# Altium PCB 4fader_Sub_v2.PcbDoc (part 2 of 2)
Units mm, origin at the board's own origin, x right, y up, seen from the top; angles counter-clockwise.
Board outline 100 x 45 mm, 2 copper layers (Top Layer, Bottom Layer); 98 components, 50 nets, 488 pads, 159 vias.
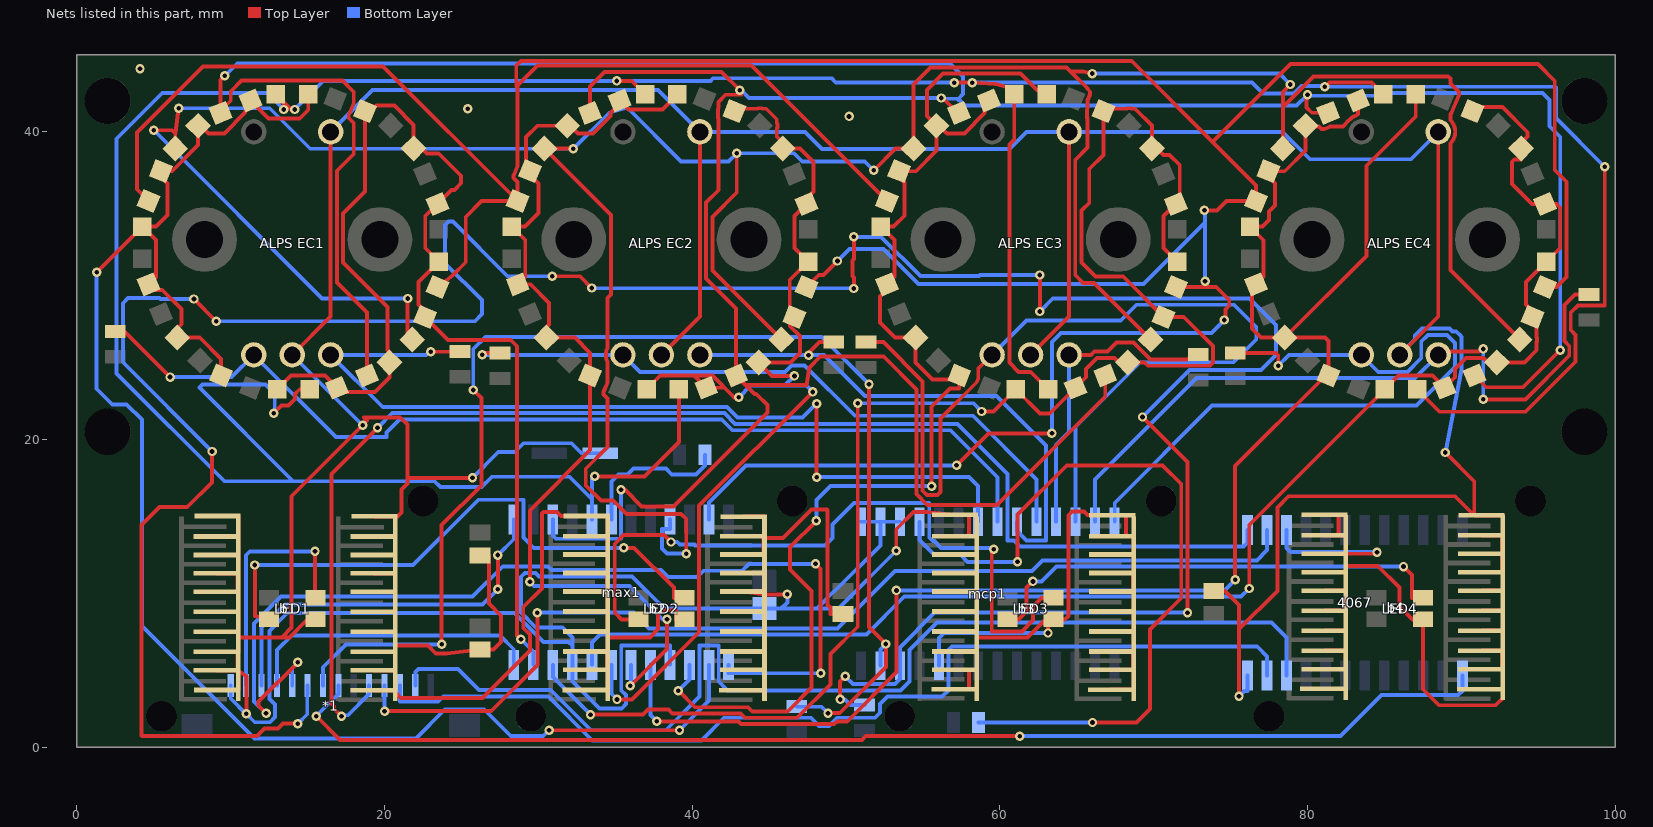
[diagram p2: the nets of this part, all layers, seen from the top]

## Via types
v1: diameter 0.61, hole 0.305, Top Layer to Bottom Layer, 159 vias

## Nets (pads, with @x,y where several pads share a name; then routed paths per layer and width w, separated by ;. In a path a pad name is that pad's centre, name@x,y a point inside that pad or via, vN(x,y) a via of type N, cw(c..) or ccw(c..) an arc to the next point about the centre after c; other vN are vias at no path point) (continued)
c1_5: *led5.2 *led13.2 *led21.2 *led29.2 *led37.2 *led45.2 *led53.2 *led61.2 max1.23 | length 259.9
  Top Layer w0.254: *led5.2@4.654,35.497 4.654,35.514 3.9,36.268 3.9,39.955 8.187,44.242 19.909,44.242 28.563,35.588 *led21.2@28.654,35.497 28.563,35.497 26.311,35.497 25.282,34.468 25.282,31.517 24.423,30.658 *led13.2@23.446,29.903 ; *led21.2@28.654,35.588 28.654,36.737 28.394,36.997 28.394,37.168 28.654,37.795 28.654,42.926 28.654,43.017 ; *led29.2@47.446,29.903 48.227,30.683 48.527,30.683 v1(49.442,31.598) ; *led37.2@52.654,35.497 43.853,44.298 29.934,44.298 28.654,43.017 ; v1(57.189,18.313) 59.271,20.396 v1(63.386,20.396) ; *led45.2@71.446,29.903 73.343,29.903 ; v1(73.3,34.9) 73.318,34.882 74.113,34.882 74.728,35.497 *led53.2@76.654,35.497 76.654,36.516 73.838,39.332 ; v1(73.343,30.284) 73.343,29.903 ; v1(74.6,27.768) 74.668,27.836 74.668,28.44 74.918,28.69 74.918,29.058 74.072,29.903 73.343,29.903 ; *led61.2@95.446,29.903 96.178,29.903 96.838,30.563 96.838,36.754 96.076,37.516 96.076,43.307 94.984,44.399 78.906,44.399 73.838,39.332 ; 28.654,43.017 28.563,42.926 28.563,43.017 28.563,44.298 28.859,44.594 68.577,44.594 73.838,39.332
  Bottom Layer w0.254: max1.23@41.1,14.8 41.1,15.905 43.508,18.313 v1(57.189,18.313) ; v1(49.442,31.598) 50.227,32.383 52.441,32.383 54.717,30.106 69.337,30.106 73.343,34.112 ; v1(63.386,20.396) 63.386,26.325 63.985,26.924 73.756,26.924 v1(74.6,27.768) ; v1(73.3,34.9) 73.343,34.857 73.343,34.112 ; v1(73.343,30.284) 73.343,34.112
c1_6: *led6.2 *led14.2 *led22.2 *led30.2 *led38.2 *led46.2 *led54.2 *led62.2 max1.21 | length 221.2
  Top Layer w0.254: v1(5,40.1) 6.174,40.1 6.396,39.878 ; *led6.2@6.396,38.906 6.396,39.878 ; v1(6.617,41.529) 6.404,39.934 6.396,39.878 ; v1(21.502,29.159) 21.502,26.796 *led14.2@21.804,26.494 ; v1@32.267,38.895 v1(32.278,38.906) *led22.2@30.396,38.906 34.71,34.593 34.71,29.413 34.5,29.204 34.5,25.969 ccw(c35.5,25.5) 34.5,25.03 34.5,23.713 34.24,23.085 34.24,22.913 34.5,22.653 34.5,19.513 33.084,18.098 33.084,17.018 34.078,16.024 34.869,16.024 35.729,15.164 39.282,15.164 39.612,14.834 v1(39.612,12.573) ; v1(42.9,38.6) 42.9,36.054 41.313,34.467 41.313,30.985 *led30.2@45.804,26.494 ; v1(51.804,37.49) 53.219,38.906 *led38.2@54.396,38.906 54.396,43.082 55.501,44.187 64.335,44.187 64.605,43.917 ; v1(66.002,43.784) 65.4,43.917 64.605,43.917 ; *led46.2@69.804,26.494 66.128,30.169 65.42,30.169 64.906,30.683 64.906,38.172 65.7,38.966 65.7,40.876 65.674,40.902 65.674,41.073 65.7,41.926 65.7,42.028 65.86,42.415 65.86,42.587 65.7,42.822 65.626,42.896 64.605,43.917 ; *led54.2@78.396,38.906 78.396,41.604 78.396,42.595 v1(78.88,43.078) ; 78.396,41.623 80.38,43.606 89.145,43.606 89.294,43.458 89.294,43.153 89.86,42.587 89.86,42.415 89.359,41.204 89.294,41.103 89.294,40.768 cw(c88.5,40) 89.294,39.233 89.294,31.003 *led62.2@93.804,26.494
  Bottom Layer w0.254: v1(5,40.1) 15.941,29.159 v1(21.502,29.159) ; v1(6.617,41.529) 12.535,41.529 15.169,38.895 32.267,38.895 v1(32.278,38.906) 34.608,41.236 35.776,41.58 39.282,38.075 42.375,38.075 42.908,38.608 46.622,38.608 47.156,38.075 51.22,38.075 v1(51.804,37.49) ; max1.21@38.56,14.8 38.56,14.173 38.037,14.173 38.037,12.903 38.367,12.573 v1(39.612,12.573) ; v1(66.002,43.784) 78.174,43.784 v1(78.88,43.078)
c1_7: *led7.2 *led15.2 *led23.2 *led31.2 *led39.2 *led47.2 *led55.2 *led63.2 max1.15 | length 258.3
  Top Layer w0.254: v1(9.614,43.637) 9.346,43.369 *led7.2@9.346,41.236 9.346,41.365 10,42.019 10,42.626 10.707,43.332 17.26,43.332 17.926,42.667 18,42.592 18,41.86 17.674,41.073 17.674,40.902 18,40.576 18,38.561 16.906,37.467 16.906,30.206 18.854,28.259 *led15.2@18.854,24.164 ; *led23.2@33.346,41.236 33.346,42.934 34.303,43.891 41.909,43.891 v1(43.1,42.7) ; v1(35.37,16.739) 35.624,16.739 36.716,15.646 38.773,15.646 44.884,21.758 44.884,22.242 44.166,22.96 44.058,22.96 43.472,23.546 ; 43.204,42.406 42.165,42.406 41.774,42.015 41.7,41.941 41.674,41.073 41.674,40.902 41.7,40.876 41.7,36.201 40.906,35.408 40.906,30.472 42.854,28.524 *led31.2@42.854,24.164 43.472,23.546 ; v1(56.2,42.2) 56.291,42.2 57.255,41.236 *led39.2@57.346,41.236 ; *led47.2@66.854,24.164 66.854,22.797 59.805,15.748 55.284,15.748 54.572,16.459 54.572,23.259 52.452,25.379 48.329,25.379 47.638,24.689 47.439,23.546 43.472,23.546 ; v1(80,42.4) 79.932,42.332 79.932,41.801 79.929,41.798 79.929,41.587 80.28,41.236 *led55.2@81.346,41.236 ; *led63.2@90.854,24.164 91.625,23.393 94.019,23.393 v1(96.432,25.806)
  Bottom Layer w0.254: v1(9.614,43.637) 10.427,44.45 56.773,44.45 57.616,43.607 57.616,42.464 57.302,42.15 56.25,42.15 v1(56.2,42.2) 43.696,42.2 43.196,42.7 v1(43.1,42.7) ; max1.15@30.94,14.8 30.94,13.759 31.154,13.546 35.379,13.546 35.379,16.729 v1(35.37,16.739) ; 57.302,42.064 57.39,42.064 ; 57.39,42.062 57.752,41.7 79.3,41.7 v1(80,42.4) 80.058,42.342 84.766,42.342 84.944,42.519 95.289,42.519 95.746,42.062 95.746,40.361 96.432,39.675 v1(96.432,25.806)
c1_8: *led8.2 *led16.2 *led24.2 *led32.2 *led40.2 *led48.2 *led56.2 *led64.2 max1.17 | length 242.9
  Top Layer w0.254: v1(12.8,21.7) 13.303,22.203 13.751,22.203 14.186,22.638 14.186,22.962 14.488,23.264 *led16.2@15.134,23.264 ; *led8.2@12.941,42.436 *led8.2@13.45,41.927 ; v1(13.45,41.453) *led8.2@13.45,41.927 ; v1(14.16,41.453) 13.924,41.453 13.687,41.69 *led8.2@13.45,41.927 ; v1(33.668,17.602) 36.894,17.602 39.134,19.842 *led32.2@39.134,23.264 ; v1(35.091,43.307) 36.07,43.307 *led24.2@36.941,42.436 ; v1(57.032,43.197) v1(58.2,43.197) ; v1@58.2,43.2 v1(58.2,43.197) ; *led48.2@63.134,23.264 62.013,24.384 61.227,24.384 60.618,24.994 60.618,39.167 60.941,39.49 *led40.2@60.941,42.436 60.468,42.909 59.727,43.103 v1(58.2,43.197) ; v1(81.115,42.926) 81.168,42.926 81.442,43.2 84.177,43.2 *led56.2@84.941,42.436 ; *led64.2@87.134,23.264 88.596,21.801 94.174,21.801 97.422,25.049 97.422,26.797 97.117,27.102 97.117,28.245 97.575,28.702 99.327,28.702 v1(99.327,37.719)
  Bottom Layer w0.254: v1(12.8,21.7) 12.866,21.766 12.866,22.962 12.256,23.571 8.167,23.571 7.963,23.368 14.052,17.279 ; v1(13.45,41.453) 12.383,42.52 5.55,42.52 2.579,39.548 2.579,24.293 9.592,17.279 14.052,17.279 ; v1(14.16,41.453) 16.014,43.307 v1(35.091,43.307) 41.195,43.307 41.372,43.484 49.044,43.484 49.332,43.197 v1(57.032,43.197) ; max1.17@33.48,14.8 33.48,16.114 ; v1(33.668,17.602) 33.48,17.414 33.48,16.114 ; v1(58.2,43.197) 76.402,43.197 77.104,42.494 79.122,42.494 79.612,42.984 81.057,42.984 v1(81.115,42.926) 96.102,42.926 96.152,42.876 96.152,40.894 v1(99.327,37.719) ; 14.052,17.279 23.254,17.279 23.626,16.908 26.308,16.908 26.978,17.577 32.017,17.577 33.48,16.114
clk11: *1.3 max1.13 | length 25.1
  Top Layer w0.254: v1(27.369,10.262) v1(27.369,12.482)
  Bottom Layer w0.254: *1.3@12,4 12,7.772 13.499,9.271 26.378,9.271 v1(27.369,10.262) ; v1(27.369,12.482) 28.4,13.513 max1.13@28.4,14.8
cs12: *1.4 max1.12 | length 19.5
  Bottom Layer w0.254: *1.4@13,4 13,6.299 13.966,7.265 27.495,7.265 28.4,6.361 max1.12@28.4,5.35
DATA: *1.2 LED1.2 | length 16.1
  Top Layer w0.254: v1(15.482,12.725) 15.482,9.7 LED1.2@15.5,9.7
  Bottom Layer w0.254: *1.2@11,4 11,4.547 10.986,4.547 10.986,12.471 11.24,12.725 v1(15.482,12.725)
din13: *1.5 max1.1 | length 64.8
  Top Layer w0.254: v1(12.3,2.2) 12.3,2.206 11.818,2.688 11.818,2.966 v1(14.364,5.512) ; v1(48.019,11.913) 48.349,11.582 v1(48.349,4.801)
  Bottom Layer w0.254: v1(12.3,2.2) 12.291,2.2 11.519,2.972 11.519,8.026 13.272,9.779 25.732,9.779 27.687,11.735 30.614,11.735 30.842,11.506 37.971,11.506 38.428,11.049 40.315,11.049 40.729,11.463 43.241,11.463 43.691,11.913 v1(48.019,11.913) ; *1.5@14,4 14,5.148 v1(14.364,5.512) ; max1.1@42.37,5.35 42.37,4.801 v1(48.349,4.801)
e0: "ALPS EC1.B1" mcp1.21 r1.1 | length 60
  Top Layer w0.254: v1(23,25.7) 24.875,25.7 r1.1@24.9,25.725 ; v1(48.095,17.551) v1(48.095,22.327)
  Bottom Layer w0.254: v1(23,25.7) 22.904,25.7 22.703,25.5 16.5,25.5 19.886,22.113 42.26,22.113 42.958,21.416 47.185,21.416 v1(48.095,22.327) ; v1(48.095,17.551) 57.996,17.551 58.58,16.967 mcp1.21@58.58,14.65
e1: "ALPS EC1.A1" mcp1.22 r2.1 | length 66.5
  Top Layer w0.254: r2.1@2.5,27.025 3.087,27.025 v1(6.058,24.054)
  Bottom Layer w0.254: v1(6.058,24.054) 10.054,24.054 11.5,25.5 16.832,20.168 20.13,20.168 20.13,20.448 20.983,21.301 41.923,21.301 42.627,20.597 56.795,20.597 59.85,17.542 mcp1.22@59.85,14.65
e2: "ALPS EC2.B1" mcp1.23 r3.1 | length 36
  Top Layer w0.254: v1(47.567,25.475) 47.635,25.543 47.635,25.676 48.284,26.325 r3.1@49.2,26.325
  Bottom Layer w0.254: 40.5,25.5 47.543,25.5 v1(47.567,25.475) ; v1@47.458,25.5 48.58,25.5 51.245,22.835 59.779,22.835 63.005,19.609 63.005,13.437 61.735,13.437 61.12,14.052 mcp1.23@61.12,14.65
e3: "ALPS EC2.A1" mcp1.24 r4.1 | length 43.7
  Top Layer w0.254: v1(26.355,25.5) 26.48,25.625 r4.1@27.5,25.625
  Bottom Layer w0.254: v1(26.355,25.5) 35.5,25.5 36.615,24.384 46.038,24.384 46.47,24.816 47.308,24.816 50.585,21.539 58.255,21.539 62.39,17.405 mcp1.24@62.39,14.65
e4: "ALPS EC3.B1" mcp1.25 r5.1 | length 20.5
  Top Layer w0.254: 64.5,25.5 65.934,25.5 66.14,25.706 66.996,25.706 67.59,26.3 68.684,26.3 69.784,25.2 72.203,25.2 72.23,25.227 72.602,25.227 r5.1@72.9,25.525
  Bottom Layer w0.254: mcp1.25@63.66,14.65 63.66,19.634 64.5,20.474 64.5,25.5
e5: "ALPS EC3.A1" mcp1.26 r6.1 | length 63.7
  Top Layer w0.254: r6.1@51.3,26.325 52.428,26.325 54.979,23.774 54.979,16.662 55.258,16.383 55.944,16.383 56.147,16.586 56.147,21.364 58.503,23.72 58.6,23.955 58.6,24.6 59.5,25.5
  Bottom Layer w0.254: 59.5,25.5 61.737,27.737 67.863,27.737 68.884,28.759 75.217,28.759 76.67,27.305 76.67,26.492 75.197,25.019 69.127,25.019 64.93,20.822 mcp1.26@64.93,14.65
e6: "ALPS EC4.B1" mcp1.27 r7.1 | length 47.1
  Top Layer w0.254: 88.5,25.5 88.5,25.806 88.6,25.706 91.154,25.706 91.332,25.884 v1(91.428,25.884) ; v1(91.428,22.606) 94.171,22.606 97.016,25.451 97.016,26.086 96.711,26.391 96.711,28.739 97.397,29.425 r7.1@98.3,29.425
  Bottom Layer w0.254: mcp1.27@66.2,14.65 66.2,17.393 72.796,23.989 86.989,23.989 88.5,25.5 ; v1(91.428,22.606) v1(91.428,25.884)
e7: "ALPS EC4.A1" mcp1.28 r8.1 | length 46.2
  Top Layer w0.254: r8.1@75.3,25.625 77.951,25.625 78.1,25.476 v1(78.1,24.8)
  Bottom Layer w0.254: mcp1.28@67.47,14.65 67.47,15.869 73.8,22.2 87.1,22.2 89.604,24.704 89.604,25.468 ccw(c88.5,25.5) 89.604,25.532 89.604,26.269 89.073,26.8 87.839,26.8 87.395,26.356 87.395,25.285 86.506,24.395 84.604,24.395 83.499,25.5 78.8,25.5 v1(78.1,24.8)
GND: 4067.12 4067.15 "ALPS EC1.C1" "ALPS EC1.W1" "ALPS EC2.C1" "ALPS EC2.W1" "ALPS EC3.C1" "ALPS EC3.W1" "ALPS EC4.C1" "ALPS EC4.W1" *1.1 b1.2 b2.2 b3.2 b4.2 C1.1 C2.2 C3.1 C4.2 C5.2 C6.1 LED1.1 LED2.1 LED3.1 LED4.1 max1.4 max1.9 mcp1.10 mcp1.15 mcp1.16 mcp1.17 pad.19 pad.20 pad.21 pad.22 pad.23 pad.24 pad.25 pad.26 pad.27 | length 675.8
  Top Layer w0.254: pad.27@9.091,4.991 b1.2@10.453,4.991 ; pad.26@9.091,6.191 b1.2@10.453,6.191 ; pad.25@9.091,7.491 b1.2@10.5,7.491 ; pad.24@9.091,8.791 b1.2@10.5,8.791 ; pad.23@9.091,10.091 b1.2@10.453,10.091 ; pad.22@9.091,11.291 10.453,11.291 b1.2@10.453,10.091 ; pad.21@9.091,12.491 10.478,12.491 b1.2@10.5,12.47 ; pad.20@9.091,13.691 b1.2@10.5,13.691 ; pad.27@9.113,3.708 10.5,3.708 b1.2@10.5,4.958 ; pad.19@9.142,15.024 10.5,15.024 b1.2@10.5,13.691 ; v1(11.016,2.164) 11.037,2.184 11.037,4.585 b1.2@10.5,4.958 ; 14,25.5 16.5,28 16.5,40 ; LED1.1@15.5,8.3 14.974,8.3 13.812,7.137 13.323,7.137 ; pad.27@19.273,3.683 b1.2@20.7,3.683 ; pad.27@19.291,4.991 b1.2@20.7,4.991 ; pad.26@19.291,6.191 b1.2@20.7,6.191 ; pad.25@19.291,7.491 b1.2@20.7,7.491 ; pad.24@19.291,8.791 b1.2@20.7,8.791 ; pad.23@19.291,10.091 b1.2@20.7,10.091 ; pad.22@19.291,11.291 b1.2@20.7,11.291 ; pad.21@19.291,12.491 b1.2@20.7,12.491 ; pad.20@19.291,13.691 20.663,13.691 b1.2@20.663,14.999 ; pad.19@19.353,14.999 b1.2@20.663,14.999 ; v1(25.718,17.501) 21.486,17.501 ; C1.1@26.2,12.45 26.785,12.45 26.785,9.322 27.567,8.54 27.567,6.827 27.09,6.35 C2.2@26.2,6.35 24.042,6.096 23.331,6.096 22.823,6.604 b1.2@20.7,6.604 ; pad.27@33.065,3.708 34.5,3.708 b2.2@34.5,6.217 ; pad.27@33.094,5.017 34.456,5.017 b2.2@34.456,6.217 ; pad.26@33.094,6.217 b2.2@34.456,6.217 ; pad.25@33.094,7.517 b2.2@34.5,7.517 ; pad.24@33.094,8.817 b2.2@34.5,8.817 ; pad.23@33.094,10.117 b2.2@34.456,10.117 ; pad.22@33.094,11.317 34.456,11.317 b2.2@34.456,10.117 ; pad.21@33.094,12.517 b2.2@34.5,12.517 ; pad.20@33.094,13.717 b2.2@34.5,13.717 ; 38,25.5 40.5,28 40.5,40 ; LED2.1@39.5,8.3 38.951,8.3 38.951,8.894 38.062,8.894 37.783,8.615 37.783,7.671 37.25,7.137 b2.2@34.5,7.137 ; pad.27@43.25,3.683 44.7,3.683 b2.2@44.7,5.017 ; pad.27@43.294,5.017 b2.2@44.7,5.017 ; pad.26@43.294,6.217 b2.2@44.7,6.217 ; pad.25@43.294,7.517 b2.2@44.7,7.517 ; pad.24@43.294,8.817 b2.2@44.7,8.817 ; pad.23@43.294,10.117 b2.2@44.7,9.931 ; pad.22@43.294,11.317 44.692,11.317 b2.2@44.692,13.717 ; pad.21@43.294,12.517 44.641,12.517 b2.2@44.641,13.717 ; pad.20@43.294,13.717 b2.2@44.641,13.717 ; pad.19@43.352,14.986 44.7,14.986 b2.2@44.7,13.589 ; v1(46.19,9.931) b2.2@44.7,9.931 ; C3.1@49.8,8.65 48.984,8.65 48.984,9.068 48.807,9.246 48.807,15.392 48.756,15.443 47.753,15.443 45.898,13.589 b2.2@44.7,13.589 ; v1(53.265,12.765) 53.265,14.161 54.395,15.291 55.233,15.291 pad.19@57.097,15.1 58.001,15.1 pad.20@58.001,13.717 ; pad.27@57.068,3.759 pad.27@58.001,3.759 ; pad.27@57.097,5.017 58.001,5.017 pad.27@58.001,3.759 ; pad.26@57.097,6.217 b3.2@58.5,6.217 ; pad.25@57.097,7.517 b3.2@58.5,7.517 ; pad.24@57.097,8.817 b3.2@58.5,8.817 ; pad.23@57.097,10.117 b3.2@58.5,10.117 ; pad.22@57.097,11.317 b3.2@58.5,11.317 ; pad.21@57.097,12.517 b3.2@58.5,12.517 ; pad.20@57.097,13.717 pad.20@58.001,13.717 ; 62,25.5 64.5,28 64.5,40 ; v1(63.132,7.417) LED3.1@63.132,8.3 ; pad.27@67.228,3.733 68.7,3.733 b3.2@68.7,6.217 ; pad.27@67.297,5.017 68.644,5.017 b3.2@68.644,6.217 ; pad.26@67.297,6.217 b3.2@68.644,6.217 ; pad.25@67.297,7.517 b3.2@68.7,7.517 ; pad.24@67.297,8.817 68.669,8.817 68.669,8.969 b3.2@68.7,9 ; pad.23@67.297,10.117 b3.2@68.644,10.117 ; pad.22@67.297,11.317 68.644,11.317 b3.2@68.644,10.117 ; pad.21@67.297,12.517 b3.2@68.7,12.517 ; pad.20@67.297,13.717 pad.20@68.212,13.717 ; C4.2@73.9,10.15 74.638,10.15 75.553,9.236 75.553,7.671 ; v1(75.553,3.302) 75.553,7.671 ; pad.27@81.02,3.784 82.5,3.784 b4.2@82.5,6.267 ; pad.27@81.1,5.067 82.462,5.067 b4.2@82.462,6.267 ; pad.26@81.1,6.267 b4.2@82.462,6.267 ; pad.25@81.1,7.567 b4.2@82.5,7.567 ; pad.24@81.1,8.867 b4.2@82.5,8.867 ; pad.23@81.1,10.167 b4.2@82.5,10.167 ; pad.22@81.1,11.367 b4.2@82.5,11.367 ; pad.21@81.1,12.567 b4.2@82.5,12.567 ; pad.20@81.1,13.767 pad.20@82.004,13.767 ; pad.19@81.1,15.1 82.004,15.1 pad.20@82.004,13.767 ; v1(84.519,12.675) 84.412,12.567 b4.2@82.5,12.567 ; 86,25.5 88.5,28 88.5,40 ; v1(88.964,19.152) 90.844,17.272 pad.19@90.844,15.062 ; pad.27@91.206,3.759 b4.2@92.7,3.759 ; pad.27@91.3,5.067 92.647,5.067 b4.2@92.647,6.267 ; pad.26@91.3,6.267 b4.2@92.647,6.267 ; pad.25@91.3,7.567 b4.2@92.7,7.567 ; pad.24@91.3,8.867 b4.2@92.7,8.867 ; pad.23@91.3,10.167 b4.2@92.7,10.167 ; pad.22@91.3,11.367 92.647,11.367 b4.2@92.647,12.567 ; pad.21@91.3,12.567 b4.2@92.647,12.567 ; pad.20@91.3,13.767 b4.2@92.647,13.767 ; b1.2@10.453,4.991 b1.2@10.5,4.958 ; b1.2@10.453,4.991 b1.2@10.453,6.191 ; b1.2@10.453,6.191 10.5,6.191 b1.2@10.5,7.137 ; b1.2@10.453,10.091 10.478,10.091 b1.2@10.5,10.07 ; b1.2@10.5,7.137 13.323,7.137 ; b1.2@10.5,7.137 b1.2@10.5,7.491 ; b1.2@10.5,7.491 b1.2@10.5,8.791 ; b1.2@10.5,8.791 b1.2@10.5,9 b1.2@10.5,10.07 ; b1.2@10.5,10.07 10.5,10.091 10.5,11.291 10.5,12.462 b1.2@10.5,12.47 ; b1.2@10.5,12.47 b1.2@10.5,13.691 ; 13.323,7.137 13.958,7.772 13.958,16.307 v1(18.575,20.924) 18.873,21.222 18.657,21.438 21.019,21.438 21.486,20.971 21.486,17.501 ; b1.2@20.663,14.999 b1.2@20.7,14.999 ; b1.2@20.7,3.683 20.7,3.556 21.055,3.2 26.378,3.2 29.452,6.274 29.452,7.315 29.02,7.747 29.02,9.099 30.239,10.318 30.239,15.189 30.341,15.291 31.217,15.291 31.484,15.024 pad.19@33.145,15.024 34.5,15.024 b2.2@34.5,13.717 ; b1.2@20.7,3.683 b1.2@20.7,4.991 ; b1.2@20.7,4.991 b1.2@20.7,6.191 ; b1.2@20.7,6.191 b1.2@20.7,6.604 ; b1.2@20.7,6.604 b1.2@20.7,7.491 ; b1.2@20.7,7.491 b1.2@20.7,8.791 ; b1.2@20.7,8.791 b1.2@20.7,9 b1.2@20.7,10.091 ; b1.2@20.7,10.091 b1.2@20.7,11.291 ; b1.2@20.7,11.291 b1.2@20.7,12.491 ; b1.2@20.7,12.491 b1.2@20.7,14.999 ; b1.2@20.7,14.999 20.854,14.999 21.095,15.24 21.095,16.741 21.486,17.132 21.486,17.501 ; b2.2@34.456,6.217 b2.2@34.5,6.217 ; b2.2@34.456,10.117 b2.2@34.5,10.117 ; b2.2@34.5,6.217 b2.2@34.5,7.137 ; b2.2@34.5,7.137 b2.2@34.5,7.517 ; b2.2@34.5,7.517 b2.2@34.5,8.817 ; b2.2@34.5,8.817 b2.2@34.5,9 b2.2@34.5,10.117 ; b2.2@34.5,10.117 34.5,11.317 b2.2@34.5,12.517 ; b2.2@34.5,12.517 b2.2@34.5,13.717 ; b2.2@44.641,13.717 b2.2@44.692,13.717 ; b2.2@44.692,13.717 44.696,12.521 44.7,11.321 b2.2@44.7,11.27 ; b2.2@44.7,5.017 b2.2@44.7,6.217 ; b2.2@44.7,6.217 b2.2@44.7,7.517 ; b2.2@44.7,7.517 b2.2@44.7,8.817 ; b2.2@44.7,8.817 b2.2@44.7,9 b2.2@44.7,9.931 ; b2.2@44.7,9.931 44.7,10.117 b2.2@44.7,11.27 ; b2.2@44.7,11.27 44.7,11.317 44.7,12.517 b2.2@44.7,13.589 ; pad.27@58.001,3.759 58.5,3.759 b3.2@58.5,6.217 ; pad.20@58.001,13.717 b3.2@58.5,13.717 ; b3.2@58.5,6.217 b3.2@58.5,7.114 ; b3.2@58.5,7.114 b3.2@58.5,7.517 ; b3.2@58.5,7.114 61.794,7.114 62.98,8.3 LED3.1@63.132,8.3 ; b3.2@58.5,7.517 b3.2@58.5,8.817 ; b3.2@58.5,8.817 b3.2@58.5,9 b3.2@58.5,10.117 ; b3.2@58.5,10.117 b3.2@58.5,11.317 ; b3.2@58.5,11.317 b3.2@58.5,12.517 ; b3.2@58.5,12.517 58.509,12.517 58.509,13.717 b3.2@58.5,13.717 ; b3.2@58.5,12.517 b3.2@58.5,13.717 ; LED3.1@63.132,8.3 LED3.1@63.5,8.3 64.218,8.3 64.453,8.534 64.453,15.074 64.682,15.303 65.47,15.303 65.698,15.075 pad.19@67.308,15.075 68.212,15.075 pad.20@68.212,13.717 ; pad.20@68.212,13.717 68.7,13.717 b3.2@68.7,12.517 ; b3.2@68.644,6.217 b3.2@68.7,6.217 ; b3.2@68.644,10.117 68.667,10.117 b3.2@68.7,10.084 ; b3.2@68.7,6.217 b3.2@68.7,7.517 ; b3.2@68.7,7.517 68.7,8.817 b3.2@68.7,9 ; b3.2@68.7,9 b3.2@68.7,10.084 ; b3.2@68.7,10.084 68.7,10.117 68.7,11.317 b3.2@68.7,12.517 ; 75.553,7.671 78.042,10.16 78.042,15.57 78.779,16.307 89.599,16.307 pad.19@90.844,15.062 ; pad.20@82.004,13.767 82.5,13.767 b4.2@82.5,12.567 ; b4.2@82.462,6.267 b4.2@82.5,6.267 ; b4.2@82.5,6.267 b4.2@82.5,7.567 ; b4.2@82.5,7.567 b4.2@82.5,8.867 ; b4.2@82.5,8.867 b4.2@82.5,9.075 b4.2@82.5,10.167 ; b4.2@82.5,10.167 b4.2@82.5,11.367 ; b4.2@82.5,11.367 b4.2@82.5,11.786 ; b4.2@82.5,11.786 84.57,11.786 85.992,10.363 85.992,9.138 86.83,8.3 LED4.1@87.5,8.3 87.516,8.3 87.516,3.761 88.558,2.72 92.219,2.72 92.7,3.2 b4.2@92.7,3.759 ; b4.2@82.5,11.786 b4.2@82.5,12.567 ; pad.19@90.844,15.062 pad.19@91.307,15.062 92.7,15.062 b4.2@92.7,11.072 ; b4.2@92.647,6.267 b4.2@92.7,6.267 ; b4.2@92.647,12.567 b4.2@92.647,13.767 ; b4.2@92.647,13.767 92.698,13.767 92.698,12.567 92.698,11.074 b4.2@92.7,11.072 ; b4.2@92.7,3.759 92.7,5.067 b4.2@92.7,6.267 ; b4.2@92.7,6.267 b4.2@92.7,7.567 ; b4.2@92.7,7.567 b4.2@92.7,8.867 ; b4.2@92.7,8.867 b4.2@92.7,9.075 b4.2@92.7,10.167 ; b4.2@92.7,10.167 b4.2@92.7,11.072
  Bottom Layer w0.254: *1.1@10,4 10,3.17 11.007,2.164 v1(11.016,2.164) ; v1@11.016,2.159 11.021,2.159 11.564,1.616 12.542,1.616 12.884,1.958 12.884,2.771 12.521,3.134 12.521,7.554 13.678,8.712 28.461,8.712 30.341,6.833 31.966,6.833 32.21,6.589 ; 14,25.5 v1(18.575,20.924) ; 16.5,40 19.22,42.72 37.779,42.72 40.5,40 47.332,40 48.445,38.887 60.618,38.887 61.73,40 78.388,40 80.17,38.218 86.718,38.218 88.5,40 ; v1(25.718,17.501) 27.394,19.177 28.468,19.177 29.045,19.754 32.15,19.754 32.805,19.1 C5.2@34.021,19.1 ; max1.4@38.56,5.35 38.56,6.604 35.391,6.604 35.391,3.685 35.7,3.375 35.7,2.794 35.421,2.515 33.963,2.515 32.21,4.267 max1.9@32.21,5.35 32.21,6.589 ; v1(46.19,9.931) 46.19,9.406 45.784,8.999 ; mcp1.15@50.96,14.65 mcp1.16@52.23,14.65 ; v1(53.265,12.765) 49.499,8.999 48.103,8.999 ; mcp1.17@53.5,14.65 mcp1.16@52.23,14.65 ; mcp1.10@56.04,5.3 56.04,7.087 56.37,7.417 v1(63.132,7.417) ; v1(75.553,3.302) 75.908,3.658 76.1,3.658 4067.12@76.1,4.65 ; 4067.15@78.64,14.1 78.64,12.94 78.906,12.675 v1(84.519,12.675) ; 86,25.5 86.989,26.489 86.989,26.762 87.433,27.206 89.241,27.206 89.437,27.011 89.675,27.011 89.936,26.75 90.01,26.675 90.01,25.537 cw(c88.5,25.5) 90.01,25.463 90.01,24.536 v1(88.964,19.152) ; 32.21,6.589 32.21,7.122 31.56,7.772 29.833,7.772 28.868,8.738 28.868,11.074 29.122,11.328 29.807,11.328 30.036,11.1 36.081,11.1 38.182,8.999 C6.1@44.7,8.999 45.784,8.999 ; 45.784,8.999 48.103,8.999 ; 48.103,8.999 49.232,10.129 49.255,10.129 52.23,13.104 mcp1.16@52.23,14.65
  other v1: 50.2,41 25.4,41.5 4.1,44.1
NetLED1_4: LED1.4 LED2.2 | length 38.4
  Top Layer w0.254: v1(11.57,11.836) 11.57,8.534 LED1.4@12.5,8.3 ; v1(35.548,12.954) 36.23,12.954 38.821,10.363 38.821,9.7 LED2.2@39.5,9.7
  Bottom Layer w0.254: v1(11.57,11.836) 21.857,11.836 26.099,16.078 29.041,16.078 29.041,13.614 29.701,12.954 v1(35.548,12.954)
NetLED2_4: LED2.4 LED3.2 | length 46.5
  Top Layer w0.254: LED2.4@36.5,8.3 35.402,8.3 34.964,8.738 34.964,13.208 35.535,13.779 38.177,13.779 v1(38.621,13.335) ; v1(59.602,12.852) 59.475,12.852 59.475,7.52 61.43,7.52 62.165,8.255 62.165,9.144 62.721,9.7 LED3.2@63.5,9.7
  Bottom Layer w0.254: v1(38.621,13.335) 39.028,13.335 39.205,13.157 40.145,13.157 40.196,13.106 48.629,13.106 49.111,13.589 49.111,14.478 50.508,15.875 55.411,15.875 55.411,13.614 55.639,13.386 55.748,13.386 56.179,12.954 59.5,12.954 v1(59.602,12.852)
NetLED3_4: LED3.4 LED4.2 | length 31
  Top Layer w0.254: LED3.4@60.5,8.3 61.227,8.3 61.745,8.818 61.745,10.363 v1(62.152,10.77) ; v1(86.246,11.735) 86.805,11.176 86.805,9.7 LED4.2@87.5,9.7
  Bottom Layer w0.254: v1(62.152,10.77) 62.711,10.77 63.676,11.735 v1(86.246,11.735)
Netmax1_18: max1.18 r9.1 | length 10
  Bottom Layer w0.254: max1.18@34.75,14.8 34.75,17.272 35.207,17.729 35.791,17.729 36.172,18.11 38.291,18.11 38.672,17.729 40.247,17.729 40.825,18.307 r9.1@40.825,19
Netmcp1_18: mcp1.18 r12.1 | length 50.7
  Top Layer w0.254: v1(61.151,12.04) 61.151,15.113 64.351,18.313 70.574,18.313 71.794,17.094 71.794,9.68 69.762,7.648 69.762,2.464 68.898,1.6 v1(66.028,1.6)
  Bottom Layer w0.254: mcp1.18@54.77,14.65 54.77,13.452 55.711,12.51 57.429,12.51 57.9,12.04 v1(61.151,12.04) ; r12.1@58.625,1.6 v1(66.028,1.6)
r1_1: *led1.1 *led2.1 *led3.1 *led4.1 *led5.1 *led6.1 *led7.1 *led8.1 max1.2 | length 106.7
  Top Layer w0.254: v1(1.283,30.86) *led4.1@4.264,33.841 ; *led5.1@5.457,37.437 5.457,37.074 5.9,36.632 5.9,34.597 5.144,33.841 *led4.1@4.264,33.841 ; *led5.1@5.55,37.437 6.183,37.437 7.881,39.136 7.881,40.335 *led6.1@7.881,40.391 8.076,40.391 8.567,39.9 9.586,39.9 10.936,41.25 10.936,41.304 11.286,41.655 *led7.1@11.286,42.039 12.457,40.869 14.491,40.869 15.041,41.418 *led8.1@15.041,42.436 ; *led1.1@9.363,24.157 9.363,25.242 7.989,26.616 *led2.1@6.522,26.616 6.522,27.208 6.8,27.486 6.8,28.468 5.55,29.718 5.029,29.718 *led3.1@4.661,30.086 5.144,30.57 5.144,32.961 *led4.1@4.264,33.841 ; v1(30.696,1.092) v1(39.173,1.092)
  Bottom Layer w0.254: v1(1.283,30.86) 1.283,23.295 2.299,22.279 3.235,22.279 4.23,21.285 4.23,7.874 11.545,0.559 22.035,0.559 23.915,2.438 26.48,2.438 28.207,0.711 30.315,0.711 v1(30.696,1.092) ; v1(39.173,1.092) 41.1,3.02 max1.2@41.1,5.35
r1_2: *led9.1 *led10.1 *led11.1 *led12.1 *led13.1 *led14.1 *led15.1 *led16.1 max1.11 | length 76.1
  Top Layer w0.254: *led16.1@13.034,23.264 13.926,24.155 16.119,24.155 *led15.1@16.914,23.361 17.186,23.089 19.368,23.089 20.319,24.039 20.319,25.678 20.194,25.803 20.194,28.615 17.313,31.496 17.313,34.699 18.737,36.123 *led9.1@18.737,41.343 19.122,41.343 19.48,41.7 20.636,41.7 21.891,40.445 *led10.1@21.891,38.919 22.43,38.919 22.749,38.6 23.526,38.6 24.984,37.142 24.984,36.658 24.544,36.218 24.344,36.218 22.645,34.519 22.645,32.45 *led12.1@23.536,31.559 22.2,30.223 22.2,28.768 22.643,28.326 *led13.1@22.643,27.963 24.138,26.467 28.207,26.467 28.614,26.06 28.614,7.264 v1(28.868,7.01)
  Bottom Layer w0.254: v1(28.868,7.01) 29.67,6.208 max1.11@29.67,5.35
r1_3: *led17.1 *led18.1 *led19.1 *led20.1 *led21.1 *led22.1 *led23.1 *led24.1 max1.6 | length 64.8
  Top Layer w0.254: v1(29.452,10.744) 29.452,15.392 33.363,19.303 *led17.1@33.363,24.157 33.363,25.626 32.373,26.616 *led18.1@30.522,26.616 30.522,27.285 30.7,27.462 30.7,28.88 29.494,30.086 *led19.1@28.661,30.086 29.147,30.573 29.147,32.958 *led20.1@28.264,33.841 29.122,33.841 30,34.719 30,36.632 *led21.1@29.457,37.174 ; *led21.1@29.457,37.437 29.2,37.695 29.2,39.657 29.934,40.391 32.076,40.391 32.567,39.9 33.563,39.9 34.7,41.037 34.7,41.234 35.286,41.82 *led23.1@35.286,42.039 35.873,41.453 38.058,41.453 *led24.1@39.041,42.436 ; v1(35.98,3.988) 38.367,6.375 v1(38.367,8.306)
  Bottom Layer w0.254: v1(29.452,10.744) 29.721,10.475 35.915,10.475 38.085,8.306 v1(38.367,8.306) ; v1(35.98,3.988) 36.02,4.028 max1.6@36.02,5.35
r1_4: *led25.1 *led26.1 *led27.1 *led28.1 *led29.1 *led30.1 *led31.1 *led32.1 max1.7 | length 72.1
  Top Layer w0.254: v1(35.116,3.099) 36.081,3.099 40.45,7.468 40.45,15.697 v1(47.841,23.089) ; *led32.1@37.034,23.264 37.926,24.155 40.119,24.155 ; 42.7,22.737 v1(43.037,22.737) ; *led25.1@42.737,41.343 42.895,41.5 44.259,41.5 44.29,41.532 44.522,41.532 44.553,41.5 44.814,41.5 45.5,40.814 45.5,40.553 45.534,40.519 45.534,40.288 45.5,40.254 45.5,39.705 45.891,39.314 *led26.1@45.891,38.919 47.023,38.919 47.9,38.041 47.9,36.119 47.439,35.659 *led27.1@47.439,35.314 46.648,34.522 46.648,32.447 *led28.1@47.536,31.559 46.343,30.366 *led29.1@46.343,27.963 ; *led29.1@46.643,27.963 *led29.1@46.343,27.963 ; v1(46.648,24.13) 45.198,24.13 *led30.1@44.319,25.009 46.394,25.009 47,25.615 47,26.724 46.343,27.381 *led29.1@46.343,27.963 ; 40.119,24.155 *led31.1@40.914,23.361 42.108,23.361 42.7,22.769 41.314,24.155 40.119,24.155
  Bottom Layer w0.254: max1.7@34.75,5.35 34.75,3.465 v1(35.116,3.099) ; v1(43.037,22.737) 43.795,23.495 46.013,23.495 ; v1(46.648,24.13) 46.013,23.495 ; v1(47.841,23.089) 47.435,23.495 46.013,23.495
r1_5: *led33.1 *led34.1 *led35.1 *led36.1 *led37.1 *led38.1 *led39.1 *led40.1 max1.3 | length 81.7
  Top Layer w0.254: v1(39.104,3.668) 40.181,2.591 43.625,2.591 43.904,2.311 46.216,2.311 47.765,3.861 47.765,10.16 46.368,11.557 46.368,13.005 v1(48.07,14.707) ; *led37.1@53.457,37.437 *led37.1@53.8,37.437 ; v1(55.563,16.967) 55.563,22.123 56.757,23.317 57.363,23.317 *led33.1@57.363,24.157 57.105,23.9 55.615,23.9 54.522,24.993 *led34.1@54.522,26.616 53.179,26.616 52.2,27.595 52.2,29.281 52.661,29.741 *led35.1@52.661,30.086 53.15,30.576 53.15,32.955 *led36.1@52.264,33.841 53.099,33.841 53.8,34.542 53.8,36.71 53.729,36.78 53.729,37.367 *led37.1@53.8,37.437 ; *led39.1@59.286,42.039 59.014,41.767 59.014,41.214 57.7,39.9 56.567,39.9 56.076,40.391 *led38.1@55.881,40.391 ; *led40.1@63.041,42.436 62.421,42.715 61.355,43.781 56.316,43.781 55.258,42.723 55.258,41.014 *led38.1@55.881,40.391 ; *led37.1@53.8,37.437 54.545,37.437 55.881,38.774 55.881,40.335 *led38.1@55.881,40.391
  Bottom Layer w0.254: v1(39.104,3.668) 39.83,4.394 max1.3@39.83,5.35 ; v1(48.07,14.707) 48.07,16.053 48.984,16.967 v1(55.563,16.967)
r1_6: *led41.1 *led42.1 *led43.1 *led44.1 *led45.1 *led46.1 *led47.1 *led48.1 max1.10 | length 103.6
  Top Layer w0.254: v1(33.389,2.108) 36.799,2.108 37.123,2.432 38.456,2.432 38.703,2.184 43.142,2.184 43.422,1.905 46.821,1.905 48.984,4.068 48.984,6.045 50.762,7.823 v1(50.762,22.352) ; v1(58.814,21.819) 59.589,21.819 *led48.1@61.034,23.264 62.606,21.692 63.245,21.692 *led47.1@64.914,23.361 65.596,24.043 65.596,24.587 66.309,25.3 67.448,25.3 67.739,25.009 69.4,25.009 69.615,24.794 73.664,24.794 73.854,24.984 73.854,26.066 71.958,27.963 *led45.1@70.643,27.963 68.024,30.582 66.231,30.582 65.313,31.5 65.313,34.87 65.816,35.373 65.816,37.569 66.737,38.49 *led41.1@66.737,41.343 66.895,41.5 68.259,41.5 68.29,41.532 68.522,41.532 68.553,41.5 68.791,41.5 69.891,40.4 *led42.1@69.891,38.919 70.23,38.919 70.649,38.5 71.038,38.5 71.7,37.838 71.7,35.574 70.651,34.525 70.651,32.444 *led44.1@71.536,31.559
  Bottom Layer w0.254: max1.10@30.94,5.35 30.94,4.557 v1(33.389,2.108) ; v1(50.762,22.352) 58.281,22.352 v1(58.814,21.819)
r1_7: *led49.1 *led50.1 *led51.1 *led52.1 *led53.1 *led54.1 *led55.1 *led56.1 max1.5 | length 112.4
  Top Layer w0.254: v1(37.696,1.676) 43.005,1.676 43.183,1.499 49.234,1.499 49.412,1.676 50.081,1.676 53.277,4.873 v1(53.277,10.185) ; v1(75.299,10.871) 75.299,18.263 *led49.1@80.887,23.851 ; *led53.1@77.457,37.437 *led53.1@77.9,37.437 ; *led49.1@81.135,24.385 *led49.1@81.363,24.157 81.363,26.394 81.141,26.616 80.328,26.616 80.084,26.616 *led50.1@78.522,26.616 ; *led55.1@83.286,42.039 83.286,41.17 83.17,41.054 ccw(c83.5,40) 82.682,40.742 82.448,40.484 82.299,40.335 82.276,40.335 81.47,40.335 81.077,40.172 80.906,40.172 80.743,40.335 79.881,40.335 79.881,38.796 78.522,37.437 *led53.1@77.9,37.437 ; *led56.1@87.041,42.436 87.041,41.003 83.833,37.795 83.833,31.927 *led50.1@78.522,26.616 ; *led53.1@77.9,37.437 77.74,37.278 77.74,36.791 77.9,36.632 77.9,35.204 77.506,34.811 77.506,34.271 77.077,33.841 *led52.1@76.264,33.841 77.153,32.952 77.153,30.579 76.4,29.826 76.4,27.194 76.979,26.616 *led50.1@78.522,26.616
  Bottom Layer w0.254: max1.5@37.29,5.35 37.29,2.083 v1(37.696,1.676) ; v1(53.277,10.185) 74.613,10.185 v1(75.299,10.871)
r1_8: *led57.1 *led58.1 *led59.1 *led60.1 *led61.1 *led62.1 *led63.1 *led64.1 max1.8 | length 97
  Top Layer w0.254: v1(76.213,10.312) 76.213,14.443 *led64.1@85.034,23.264 85.926,24.155 88.119,24.155 *led63.1@88.914,23.361 89.599,24.046 89.599,24.587 90.312,25.3 91.448,25.3 91.739,25.009 94.11,25.009 94.9,25.799 94.9,26.347 94.932,26.378 94.932,26.61 94.9,26.641 94.9,27.705 *led61.1@94.643,27.963 94.643,28.326 94.2,28.768 94.2,30.223 *led60.1@95.536,31.559 96.432,32.454 96.432,35.06 96.178,35.314 *led59.1@95.439,35.314 94.595,35.314 93.3,36.609 93.3,38.053 93.449,38.202 93.891,38.202 93.891,39.277 94.3,39.686 94.3,39.969 92.669,41.6 90.995,41.6 *led57.1@90.737,41.343
  Bottom Layer w0.254: max1.8@33.48,5.35 33.48,6.797 33.998,7.315 51.321,7.315 53.785,9.779 75.68,9.779 v1(76.213,10.312)
S0: 4067.10 *1.13 | length 71.9
  Bottom Layer w0.254: *1.13@22,4 22,4.877 22.203,5.08 24.778,5.08 26.15,3.708 30.807,3.708 33.424,1.092 38.281,1.092 40.471,3.282 40.471,6.604 41.729,6.604 41.729,4.267 42.307,3.689 53.537,3.689 54.115,4.267 54.115,6.299 55.919,8.103 77.649,8.103 78.64,7.112 4067.10@78.64,4.65
S1: 4067.11 *1.12 | length 65.1
  Bottom Layer w0.254: *1.12@21,4 21,2.946 23.483,2.946 23.816,3.28 30.653,3.28 33.501,0.432 40.602,0.432 42.076,1.905 47.718,1.905 48.244,1.379 48.886,1.379 49.412,1.905 51.88,1.905 52.21,2.235 52.21,2.8 52.693,3.283 56.249,3.283 56.655,3.689 56.655,6.299 56.884,6.528 76.735,6.528 77.37,5.893 4067.11@77.37,4.65
S2: 4067.14 *1.11 | length 67.5
  Top Layer w0.254: v1(20.003,2.337) 26.937,2.337 29.934,5.334 v1(29.934,8.738)
  Bottom Layer w0.254: *1.11@20,4 20,2.34 v1(20.003,2.337) ; v1(29.934,8.738) 36.188,8.738 37.204,7.722 49.442,7.722 53.175,11.455 62.091,11.455 62.777,12.141 76.71,12.141 77.37,12.802 4067.14@77.37,14.1
S3: 4067.13 *1.10 | length 87.2
  Top Layer w0.254: v1(17.2,2) 17.2,2.014 16.722,2.492 16.722,2.671 16.549,2.845 16.549,17.755 v1(19.546,20.752)
  Bottom Layer w0.254: v1(17.2,2) 17.268,2.068 17.618,2.068 19,3.45 *1.10@19,4 ; v1(19.546,20.752) 20.501,21.707 42.092,21.707 42.796,21.003 57.238,21.003 60.491,17.75 60.491,13.437 60.922,13.437 61.329,13.03 75.846,13.03 76.1,13.284 4067.13@76.1,14.1
SCL: *1.6 mcp1.12 r11.1 | length 196.9
  Top Layer w0.254: v1(7.608,29.134) v1(9.056,27.686) ; v1(8.789,19.215) 8.789,17.209 7.176,15.596 5.373,15.596 4.204,14.427 4.204,0.737 4.23,0.711 11.697,0.711 12.195,1.209 13.074,1.209 13.389,1.524 v1(14.364,1.524) ; v1(30.9,30.607) 32.703,30.607 v1(33.465,29.845) ; v1(49.619,3.099) 49.619,4.267 v1(49.953,4.6) ; v1(50.508,29.816) 50.508,30.536 50.416,30.629 50.416,31.621 50.508,31.713 v1(50.508,33.172) ; v1(62.599,28.321) v1(62.599,30.691) ; v1(69.279,21.463) 72.2,18.542 v1(72.2,8.738)
  Bottom Layer w0.254: v1(7.608,29.134) 5.426,29.134 5.376,29.184 3.315,29.184 2.985,28.854 2.985,25.019 v1(8.789,19.215) ; v1(9.056,27.686) 25.87,27.686 26.328,28.143 26.328,29.058 23.94,31.445 23.94,33.934 24.169,34.163 24.448,34.163 28.004,30.607 v1(30.9,30.607) ; v1(14.364,1.524) 14.974,2.134 14.974,3.454 15,3.454 *1.6@15,4 ; v1(33.465,29.845) 33.48,29.83 50.494,29.83 v1(50.508,29.816) ; v1(49.619,3.099) 49.931,3.099 50.305,2.725 r11.1@51.2,2.725 ; v1(49.953,4.6) 50.458,4.096 53.175,4.096 53.5,4.42 mcp1.12@53.5,5.3 53.5,6.479 55.758,8.738 v1(72.2,8.738) ; v1(50.508,33.172) 52.286,33.172 54.846,30.613 58.635,30.613 58.713,30.691 v1(62.599,30.691) ; v1(62.599,28.321) 63.443,29.165 76.233,29.165 77.966,27.432 77.966,25.492 76.985,24.511 72.327,24.511 v1(69.279,21.463)
SDA: *1.7 mcp1.13 r10.1 | length 84.9
  Top Layer w0.254: v1(23.711,6.68) 23.711,14.427 26.302,17.018 26.302,22.682 v1(25.769,23.216) ; v1(48.832,2.21) 49.594,2.21 52.591,5.207 v1(52.591,6.706) 51.499,7.798 v1(51.499,23.597)
  Bottom Layer w0.254: *1.7@16,4 16,5.192 17.488,6.68 v1(23.711,6.68) ; v1(25.769,23.216) 25.769,25.883 26.556,26.67 48.426,26.67 v1(51.499,23.597) ; r10.1@46.8,2.625 48.417,2.625 v1(48.832,2.21) ; mcp1.13@52.23,5.3 52.23,6.344 v1(52.591,6.706)
Z: 4067.1 *1.8 | length 80.1
  Top Layer w0.254: v1(15.558,2.012) 17.113,0.457 51.032,0.457 51.286,0.711 v1(61.303,0.711)
  Bottom Layer w0.254: v1(15.558,2.012) 17,3.454 *1.8@17,4 ; v1(61.303,0.711) 82.137,0.711 84.804,3.378 89.791,3.378 90.07,3.658 4067.1@90.07,4.65
pads on no net: 4067.16 4067.17 4067.18 4067.19 4067.20 4067.21 4067.22 4067.23 "ALPS EC1.MH1" "ALPS EC1.MH2" "ALPS EC2.MH1" "ALPS EC2.MH2" "ALPS EC3.MH1" "ALPS EC3.MH2" "ALPS EC4.MH1" "ALPS EC4.MH2" *1.9 *1.15 *1.16 LED4.4 max1.24 mcp1.1 mcp1.2 mcp1.3 mcp1.4 mcp1.5 mcp1.6 mcp1.7 mcp1.8 mcp1.11 mcp1.14 mcp1.19 mcp1.20

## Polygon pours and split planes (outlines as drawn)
GND on Top Layer "NONET_L-01_P-001" (solid, remove dead copper, pour order 0): 0,45 100,45 100,0 0,0
GND on Bottom Layer "NONET_L-01_P-001" (solid, remove dead copper, pour order 1): 0,45 100,45 100,0 0,0

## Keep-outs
Keep-Out Layer:
  the board outline again, w0.254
